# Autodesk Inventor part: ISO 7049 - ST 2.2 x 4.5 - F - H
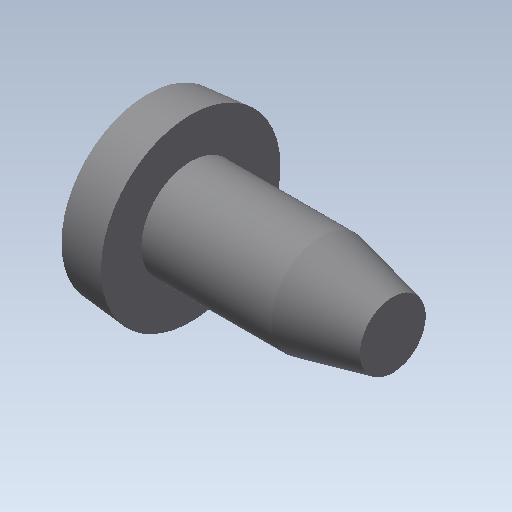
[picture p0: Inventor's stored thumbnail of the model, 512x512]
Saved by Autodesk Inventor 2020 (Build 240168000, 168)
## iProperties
Shininess: 20.0
Angle Display Precision: 2
Document Length Units: 11269
Document Angle Units: 11279
Document Time Units: 11290
Document Mass Units: 11283
Document Length Units Precision: 3
Document Angle Units Precision: 2
Created: 2002-01
Part Number: ISO 7049 - ST 2.2 x 4.5 - F - H
Material: Générique
Catalog Web Link: file:///C:/Program Files/Autodesk/Inventor 5/Content/Iso/index.htm?doNavigateId=B644153E-6486-4C49-BA92-F814F384E778|E6B68DE9D40241F9B23975AE3FB91F3E|true
Description: Vis à métaux
Document SubType Name: Standard Catalog Part
Standard: ISO 7049 - ST 2.2 x 4.5 - F - H
Designer: Philippe
Density: 1 g/cm^3
Appearance: Par défaut
Mass: 0.0299979 g
Surface Area: 0.691879 cm^2
Volume: 0.0299979 cm^3
Density: 0.0
Volumn: 0.0
Area: 0.0
PropertySet Name: Model Information
Control State: 0
Master: False
Checked Out: False
CLASSIFICATION: 31161506 un/spsc
MANUFACTURER: ISO Système de normes
Author: Philippe
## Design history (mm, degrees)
feature "Base1"
node "Solide1"
node "Corps solides"
node "Corps surfaciques"
